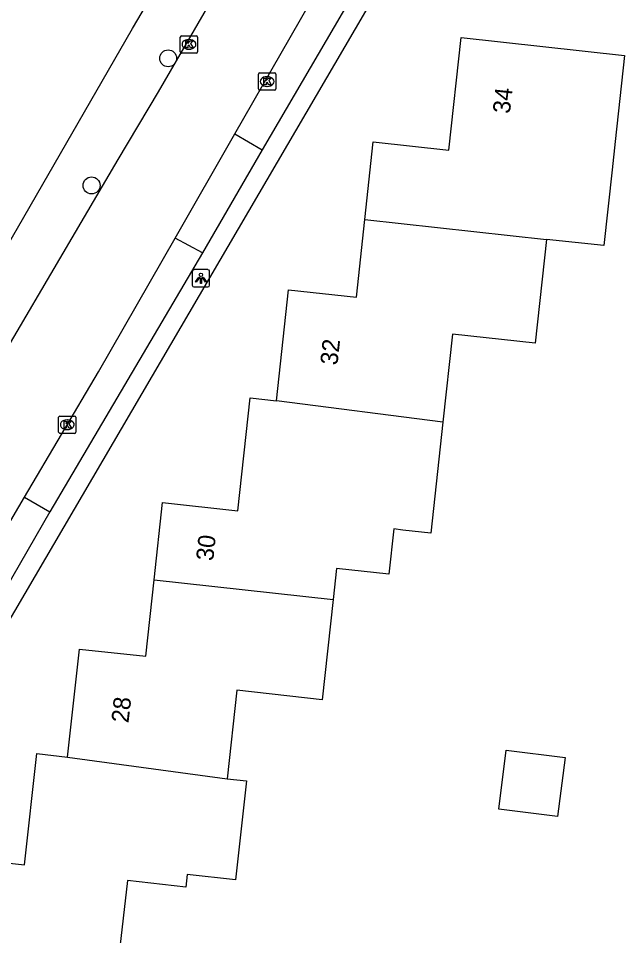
# Model space of a CAD drawing. Extents: x 162398 to 163643, y 386453 to 387397.
# Drawn here: x 162893.9 to 162929, y 386684.2 to 386737.2 of the extents above; entities that cross this region are included whole.
import ezdxf

# ---------------------------------------------------------------- set-up
doc = ezdxf.new("R2010")
doc.units = 0
for name, color, linetype in [('IMGEO_Boom', 7, 'Continuous'), ('IMGEO_Kolk', 7, 'Continuous'), ('IMGEO_Lichtpunt', 7, 'Continuous'), ('IMGEO_Pand', 7, 'Continuous'), ('IMGEO_Pand_nummerreeks', 7, 'Continuous'), ('IMGEO_Rijbaan_lokaal_open', 7, 'Continuous'), ('IMGEO_Voetpad_open', 7, 'Continuous')]:
    doc.layers.add(name, color=color, linetype=linetype)

msp = doc.modelspace()

# ---------------------------------------------------------------- linework, layer by layer
at = {"layer": 'IMGEO_Boom'}
for centre in [(162902.597, 386734.918), (162898.177, 386727.576)]:
    msp.add_circle(centre, 0.489, dxfattribs=at)
at = {"layer": 'IMGEO_Kolk'}
for p, q in [((162903.298, 386735.295), (162903.298, 386736.147)), ((162903.373, 386736.221), (162904.225, 386736.221)), ((162903.786, 386736.001), (162903.811, 386736.001)), ((162904.299, 386736.147), (162904.299, 386735.295)), ((162904.225, 386735.221), (162903.373, 386735.221)), ((162903.809, 386735.441), (162903.784, 386735.441)), ((162907.811, 386733.152), (162907.811, 386734.004)), ((162907.886, 386734.078), (162908.738, 386734.078)), ((162908.812, 386734.004), (162908.812, 386733.152)), ((162908.299, 386733.858), (162908.324, 386733.858)), ((162908.738, 386733.078), (162907.886, 386733.078)), ((162908.322, 386733.298), (162908.297, 386733.298)), ((162896.27, 386713.322), (162896.27, 386714.174)), ((162896.345, 386714.248), (162897.197, 386714.248)), ((162896.758, 386714.028), (162896.783, 386714.028)), ((162897.271, 386714.174), (162897.271, 386713.322)), ((162897.197, 386713.248), (162896.345, 386713.248)), ((162896.781, 386713.468), (162896.756, 386713.468))]:
    msp.add_line(p, q, dxfattribs=at)
for points in [[(162903.298, 386735.295), (162903.298, 386736.147)], [(162903.373, 386736.221), (162904.225, 386736.221)], [(162904.299, 386736.147), (162904.299, 386735.295)], [(162903.619, 386735.921), (162903.742, 386735.921), (162903.742, 386735.77), (162903.872, 386735.921), (162904.036, 386735.921), (162903.89, 386735.77), (162904.043, 386735.521), (162903.891, 386735.521), (162903.806, 386735.685), (162903.742, 386735.618), (162903.742, 386735.521), (162903.619, 386735.521), (162903.619, 386735.921)], [(162904.225, 386735.221), (162903.373, 386735.221)], [(162907.811, 386733.152), (162907.811, 386734.004)], [(162907.886, 386734.078), (162908.738, 386734.078)], [(162908.812, 386734.004), (162908.812, 386733.152)], [(162908.132, 386733.778), (162908.255, 386733.778), (162908.255, 386733.627), (162908.385, 386733.778), (162908.549, 386733.778), (162908.403, 386733.627), (162908.556, 386733.378), (162908.404, 386733.378), (162908.319, 386733.542), (162908.255, 386733.475), (162908.255, 386733.378), (162908.132, 386733.378), (162908.132, 386733.778)], [(162908.738, 386733.078), (162907.886, 386733.078)], [(162896.27, 386713.322), (162896.27, 386714.174)], [(162896.345, 386714.248), (162897.197, 386714.248)], [(162896.591, 386713.948), (162896.714, 386713.948), (162896.714, 386713.797), (162896.844, 386713.948), (162897.008, 386713.948), (162896.862, 386713.797), (162897.015, 386713.548), (162896.863, 386713.548), (162896.778, 386713.712), (162896.714, 386713.645), (162896.714, 386713.548), (162896.591, 386713.548), (162896.591, 386713.948)], [(162897.271, 386714.174), (162897.271, 386713.322)], [(162897.197, 386713.248), (162896.345, 386713.248)]]:
    msp.add_lwpolyline(points, dxfattribs=at)
for centre, start, end in [((162903.375, 386736.145), 91.552, 178.448), ((162903.375, 386736.145), 91.552, 178.448), ((162904.223, 386736.145), 1.552, 88.448), ((162904.223, 386736.145), 1.552, 88.448), ((162903.375, 386735.297), 181.552, 268.448), ((162903.375, 386735.297), 181.552, 268.448), ((162904.223, 386735.297), 271.552, 358.448), ((162904.223, 386735.297), 271.552, 358.448), ((162907.888, 386734.002), 91.552, 178.448), ((162907.888, 386734.002), 91.552, 178.448), ((162908.736, 386734.002), 1.552, 88.448), ((162908.736, 386734.002), 1.552, 88.448), ((162907.888, 386733.154), 181.552, 268.448), ((162907.888, 386733.154), 181.552, 268.448), ((162908.736, 386733.154), 271.552, 358.448), ((162908.736, 386733.154), 271.552, 358.448), ((162896.347, 386714.172), 91.552, 178.448), ((162896.347, 386714.172), 91.552, 178.448), ((162897.195, 386714.172), 1.552, 88.448), ((162897.195, 386714.172), 1.552, 88.448), ((162896.347, 386713.324), 181.552, 268.448), ((162896.347, 386713.324), 181.552, 268.448), ((162897.195, 386713.324), 271.552, 358.448), ((162897.195, 386713.324), 271.552, 358.448)]:
    msp.add_arc(centre, 0.0765, start, end, dxfattribs=at)
for centre, major_axis, ratio, start_param, end_param in [((162903.785, 386735.721), (-0.387, 0.002), 0.722429, 4.712389, 7.853982), ((162903.81, 386735.721), (-0.39, 0.002), 0.717154, 1.570796, 4.712389), ((162908.298, 386733.578), (-0.387, 0.002), 0.722429, 4.712389, 7.853982), ((162908.323, 386733.578), (-0.39, 0.002), 0.717154, 1.570796, 4.712389), ((162896.757, 386713.748), (-0.387, 0.002), 0.722429, 4.712389, 7.853982), ((162896.782, 386713.748), (-0.39, 0.002), 0.717154, 1.570796, 4.712389)]:
    msp.add_ellipse(centre, major_axis=major_axis, ratio=ratio, start_param=start_param, end_param=end_param, dxfattribs=at)
at = {"layer": 'IMGEO_Lichtpunt'}
for p, q in [((162903.992, 386722.611), (162903.992, 386721.804)), ((162903.992, 386722.611), (162903.992, 386721.804)), ((162904.894, 386722.706), (162904.086, 386722.706)), ((162904.894, 386722.706), (162904.086, 386722.706)), ((162904.988, 386721.804), (162904.988, 386722.611)), ((162904.988, 386721.804), (162904.988, 386722.611)), ((162904.086, 386721.71), (162904.894, 386721.71)), ((162904.086, 386721.71), (162904.894, 386721.71))]:
    msp.add_line(p, q, dxfattribs=at)
for points in [[(162904.366, 386722.275), (162904.405, 386722.247), (162904.217, 386721.985), (162904.179, 386722.012), (162904.366, 386722.275)], [(162904.468, 386722.227), (162904.515, 386722.227), (162904.515, 386721.905), (162904.468, 386721.905), (162904.468, 386722.227)], [(162904.578, 386722.247), (162904.616, 386722.274), (162904.803, 386722.012), (162904.764, 386721.984), (162904.578, 386722.247)]]:
    msp.add_lwpolyline(points, dxfattribs=at)
msp.add_circle((162904.491, 386722.409), 0.0994, dxfattribs=at)
for centre, start, end in [((162904.086, 386722.611), 90, 180), ((162904.086, 386722.611), 90, 180), ((162904.894, 386722.611), 0, 90), ((162904.894, 386722.611), 0, 90), ((162904.086, 386721.804), 180, 270), ((162904.086, 386721.804), 180, 270), ((162904.894, 386721.804), 270, 0), ((162904.894, 386721.804), 270, 360)]:
    msp.add_arc(centre, 0.0946, start, end, dxfattribs=at)
at = {"layer": 'IMGEO_Pand'}
for points in [[(162913.958, 386725.6), (162914.448, 386730.091), (162918.809, 386729.616), (162919.518, 386736.116), (162928.964, 386735.085), (162928.422, 386730.115), (162928.244, 386728.48), (162927.766, 386724.093), (162924.444, 386724.456)], [(162908.85, 386715.136), (162909.548, 386721.538), (162913.469, 386721.11), (162913.958, 386725.6)], [(162913.958, 386725.6), (162924.444, 386724.456)], [(162924.444, 386724.456), (162923.789, 386718.45), (162919.016, 386718.97), (162918.462, 386713.889)], [(162901.78, 386704.782), (162902.268, 386709.253), (162906.621, 386708.779), (162907.333, 386715.302), (162908.85, 386715.136)], [(162918.462, 386713.889), (162908.85, 386715.136)], [(162918.462, 386713.889), (162917.764, 386707.488), (162916.157, 386707.663), (162915.627, 386707.721), (162915.343, 386705.114), (162912.325, 386705.443), (162912.13, 386703.652)], [(162896.789, 386694.543), (162897.484, 386700.786), (162901.299, 386700.37), (162901.78, 386704.782)], [(162901.78, 386704.782), (162912.13, 386703.652)], [(162912.13, 386703.652), (162911.498, 386697.858), (162906.571, 386698.405), (162906.001, 386693.285)], [(162889.475, 386684.194), (162889.986, 386688.788), (162894.3, 386688.308), (162895.015, 386694.741), (162896.789, 386694.543)], [(162922.118, 386694.951), (162925.523, 386694.526), (162925.095, 386691.104), (162921.691, 386691.529), (162922.118, 386694.951)], [(162896.789, 386694.543), (162906.001, 386693.285)], [(162906.001, 386693.285), (162907.124, 386693.16), (162906.489, 386687.452), (162903.703, 386687.762), (162903.622, 386687.03), (162900.242, 386687.406), (162899.758, 386683.052)]]:
    msp.add_lwpolyline(points, dxfattribs=at)
at = {"layer": 'IMGEO_Rijbaan_lokaal_open'}
for points in [[(162924.748, 386772.326), (162923.585, 386770.172), (162916.906, 386758.651), (162914.448, 386754.399), (162902.012, 386732.978), (162899.696, 386729.077), (162891.884, 386715.828)], [(162906.451, 386730.546), (162919.39, 386753.115), (162919.621, 386753.313)], [(162903.004, 386724.533), (162906.451, 386730.546)], [(162906.451, 386730.546), (162908.024, 386729.629)], [(162908.024, 386729.629), (162904.58, 386723.682)], [(162894.3, 386709.561), (162898.573, 386716.804), (162903.004, 386724.533)], [(162904.58, 386723.682), (162903.004, 386724.533)], [(162890.79, 386703.612), (162894.3, 386709.561)], [(162894.3, 386709.561), (162895.758, 386708.719)], [(162895.758, 386708.719), (162892.276, 386702.679)]]:
    msp.add_lwpolyline(points, dxfattribs=at)
at = {"layer": 'IMGEO_Voetpad_open'}
for points in [[(162889.067, 386716.747), (162900.547, 386736.644), (162908.437, 386750), (162912.129, 386756.249)], [(162921.361, 386750.255), (162921.212, 386750), (162863.497, 386651.323), (162799.834, 386651.914)], [(162919.916, 386749.941), (162908.024, 386729.629)], [(162904.58, 386723.682), (162895.758, 386708.719)]]:
    msp.add_lwpolyline(points, dxfattribs=at)

# ---------------------------------------------------------------- texts
at = {"layer": 'IMGEO_Pand_nummerreeks'}
for s, rotation, p in [('34', 83.7722, (162922.334, 386731.689)), ('32', 83.7777, (162912.37, 386717.158)), ('30', 83.7963, (162905.197, 386705.845)), ('28', 83.6477, (162900.305, 386696.484))]:
    msp.add_text(s, height=1, rotation=rotation, dxfattribs=at).set_placement(p)

doc.saveas('drawing.dxf')
